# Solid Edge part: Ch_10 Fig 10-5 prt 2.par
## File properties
Author: Robert a Rhodes jr
Template: NORMENG.PAR
Last saved by: Cadcim
Revision: 2
Application: Solid Edge
Accuracy: 0.99
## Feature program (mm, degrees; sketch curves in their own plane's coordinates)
sketch for "unnamed Protrusion 1" plane through (0, 0, 0) normal (0, 0, 1) x-axis (1, 0, 0)
  line (-50.8, 46.0858) -> (-50.8, -55.5142)
  line (-50.8, -55.5142) -> (50.8, -55.5142)
  line (50.8, -55.5142) -> (50.8, 46.0858)
  line (50.8, 46.0858) -> (-50.8, 46.0858)
extrude "unnamed Protrusion 1" add finite 12.7 along +normal
sketch for "Hole_1" plane through (0, -4.7142, 12.7) normal (0, 0, 1) x-axis (1, 0, 0)
  hole centre (-38.1, -38.1) bore radius 3.175
hole "Hole_1" diameter 6.35 through
sketch for "unnamed Hole 1" plane through (0, -4.7142, 12.7) normal (0, 0, 1) x-axis (1, 0, 0)
  hole centre (38.1, -38.1) bore radius 3.175
hole "unnamed Hole 1" through
sketch for "unnamed Hole 2" plane through (0, -4.7142, 12.7) normal (0, 0, 1) x-axis (1, 0, 0)
  hole centre (38.1, 38.1) bore radius 3.175
hole "unnamed Hole 2" through
sketch for "unnamed Hole 3" plane through (0, -4.7142, 12.7) normal (0, 0, 1) x-axis (1, 0, 0)
  hole centre (-38.1, 38.1) bore radius 3.175
  dimension (linear) = 38.1
hole "unnamed Hole 3" through
pattern "unnamed Pattern 1" of "Hole_1", "unnamed Hole 1", "unnamed Hole 2", "unnamed Hole 3"
sketch for "Hole_5" plane through (0, -4.7142, 12.7) normal (0, 0, 1) x-axis (1, 0, 0)
  hole centre (0, 0) bore radius 12.7
hole "Hole_5" diameter 25.4 through
sketch for "Hole_6" plane through (0, -4.7142, 12.7) normal (0, 0, 1) x-axis (1, 0, 0)
  hole centre (-20.6375, 0) bore radius 2.3812
  dimension (linear) = 20.6375
hole "Hole_6" diameter 4.7625 through
pattern "unnamed Pattern 2" of "Hole_6"
pattern "unnamed Pattern 3"
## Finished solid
Body 1: solid body, 15 faces, 30 edges, 8 vertices.
  Faces by surface: cylinder 9, plane 6
  Edges by curve: circle 18, line 12
Bounding box of the edges (mm): 101.600 x 101.600 x 12.700, from (-50.8, -55.5142, 0) to (50.8, 46.0858, 12.7).
Cylindrical faces by radius (mm): R2.3812 x4, R3.175 x4, R12.7 x1
Planar faces by outward normal: +x 1, +y 1, +z 1, -x 1, -y 1, -z 1
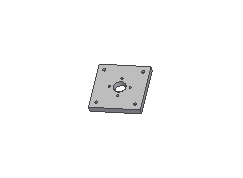
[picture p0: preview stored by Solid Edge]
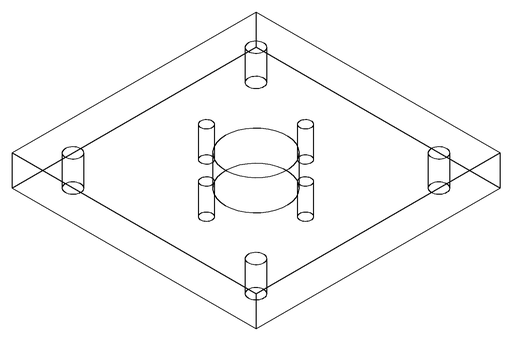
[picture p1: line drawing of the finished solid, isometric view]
